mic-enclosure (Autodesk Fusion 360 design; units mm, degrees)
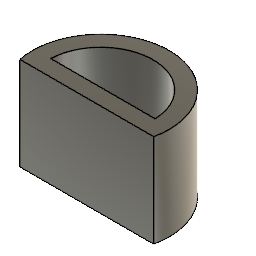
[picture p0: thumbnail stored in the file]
sketch "Sketch1" plane through (0, 0, 0) normal (0, 0, 1) x axis (1, 0, 0)
  line L1 (16.5279, 0) -> (0, 0)
  arc A1 centre (8.2639, 1.7361) radius 8.4443 clockwise from (0, 0) to (16.5279, 0)
  point P1 (0, 0)
  point P2 (0, 0)
  coincident P1 P2
  horizontal L1
extrude "Extrude1" new body sketch "Sketch1" along normal blind 11.5
sketch "Sketch2" plane through (0, 0, 11.5) normal (0, 0, 1) x axis (-1, 0, 0)
  line L1 (-16.5279, 0) -> (0, 0)
  line L2 (-14.7029, -2) -> (-1.825, -2)
  arc A1 centre (-8.2639, -1.7361) radius 8.4443 clockwise from (0, 0) to (-16.5279, 0)
  arc A2 centre (-8.2639, -1.7361) radius 6.4443 clockwise from (-1.825, -2) to (-14.7029, -2)
  dimension "d3" = -2
extrude "Extrude2" cut sketch "Sketch2" profile of A2 L2 to an object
